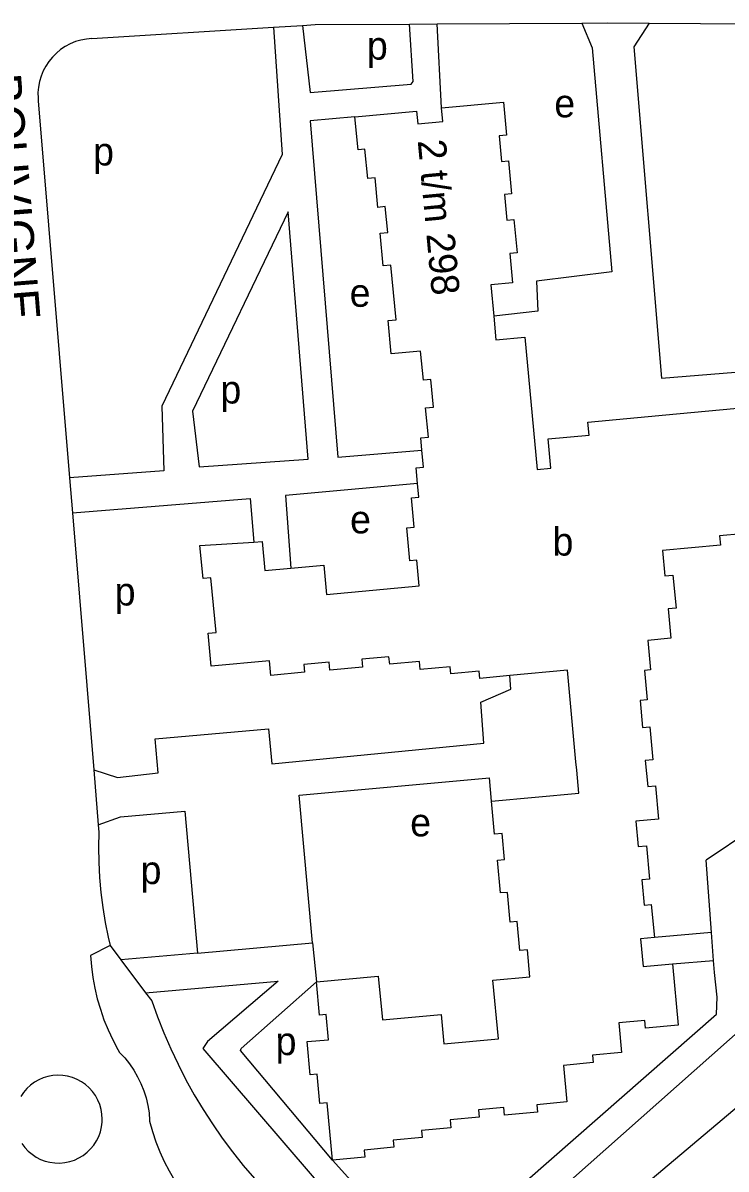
# Model space of a CAD drawing. Extents: x 157794 to 159375, y 380877 to 382306.
# Drawn here: x 158233.2 to 158333.5, y 381095.2 to 381258.6 of the extents above; entities that cross this region are included whole.
import ezdxf

# ---------------------------------------------------------------- set-up
doc = ezdxf.new("R2010")
doc.units = 0
for name, color, linetype in [('BLT_Basislijn', 7, 'Continuous'), ('BLT_Bebouwing', 7, 'Continuous'), ('BLT_Centroide', 7, 'Continuous'), ('BLT_Huisnummer_reeks', 7, 'Continuous'), ('BLT_Straatnaam', 7, 'Continuous')]:
    doc.layers.add(name, color=color, linetype=linetype)

msp = doc.modelspace()

# ---------------------------------------------------------------- linework, layer by layer
at = {"layer": 'BLT_Basislijn'}
for p, q in [((158243.03, 381256.36), (158268.94, 381257.97)), ((158268.94, 381257.97), (158273.07, 381258.22)), ((158288.34, 381258.42), (158292.29, 381258.44)), ((158292.29, 381258.44), (158312.89, 381258.56)), ((158292.9, 381246.48), (158292.29, 381258.44)), ((158322.49, 381258.55), (158363.87, 381258.34)), ((158235.37, 381247.47), (158239.83, 381193.72)), ((158239.83, 381193.72), (158240.24, 381188.74)), ((158240.24, 381188.74), (158243.28, 381152.07)), ((158243.28, 381152.07), (158243.93, 381144.25)), ((158300.04, 381147.61), (158299.74, 381150.93)), ((158343.5, 381147.91), (158330.66, 381139.21)), ((158243.93, 381144.25), (158244.01, 381143.21)), ((158331.42, 381128.87), (158330.66, 381139.21)), ((158331.42, 381128.87), (158323.26, 381128.16)), ((158245.62, 381127.05), (158242.83, 381125.61)), ((158245.62, 381127.05), (158247.15, 381125.01)), ((158274.48, 381127.4), (158275.06, 381121.86)), ((158258.07, 381125.96), (158247.15, 381125.01)), ((158247.15, 381125.01), (158250.69, 381120.3)), ((158325.83, 381124.43), (158331.71, 381124.89)), ((158250.69, 381120.3), (158269.57, 381121.95)), ((158250.69, 381120.3), (158251.55, 381119.17))]:
    msp.add_line(p, q, dxfattribs=at)
for points in [[(158268.94, 381257.97), (158270.17, 381239.84), (158252.98, 381203.96), (158253.3, 381194.7), (158239.83, 381193.72)], [(158273.07, 381258.22), (158274.16, 381248.67), (158288.55, 381249.83), (158288.86, 381250.21), (158288.34, 381258.42)], [(158273.07, 381258.22), (158274.88, 381258.34), (158288.34, 381258.42)], [(158312.89, 381258.56), (158314.38, 381255.03), (158317.19, 381223.11), (158306.42, 381221.76), (158306.64, 381217.47), (158300.35, 381216.76)], [(158312.89, 381258.56), (158316.61, 381258.58), (158322.49, 381258.55)], [(158322.49, 381258.55), (158320.33, 381255.19), (158324.26, 381207.94), (158344.81, 381209.61)], [(158243.03, 381256.36), (158242.23, 381256.29), (158241.44, 381256.14), (158240.68, 381255.92), (158239.94, 381255.61), (158239.23, 381255.24), (158238.56, 381254.8), (158237.95, 381254.29), (158237.38, 381253.72), (158236.88, 381253.1), (158236.43, 381252.44), (158236.06, 381251.73), (158235.76, 381250.99), (158235.54, 381250.22), (158235.39, 381249.43), (158235.33, 381248.64), (158235.34, 381247.84), (158235.37, 381247.47)], [(158280.55, 381245.2), (158274.15, 381244.64), (158278.12, 381196.66), (158290.1, 381197.66)], [(158271.04, 381231.66), (158257.39, 381203.25), (158258.32, 381195.29), (158273.89, 381196.36), (158271.04, 381231.66)], [(158289.48, 381192.92), (158270.64, 381191.19), (158271.41, 381180.84)], [(158240.24, 381188.74), (158265.6, 381190.76), (158266.13, 381184.57)], [(158243.28, 381152.07), (158246.66, 381151.01), (158252.46, 381151.67), (158252.03, 381156.53), (158268.23, 381157.94), (158268.7, 381152.93), (158298.93, 381155.88), (158298.48, 381161.72), (158302.78, 381163.59), (158302.66, 381165.52)], [(158274.48, 381127.4), (158272.6, 381148.49), (158299.74, 381150.93)], [(158243.93, 381144.25), (158247.09, 381145.38), (158256.28, 381146.19), (158258.07, 381125.96)], [(158244.01, 381143.21), (158243.96, 381141.06), (158243.99, 381138.91), (158244.11, 381136.75), (158244.3, 381134.61), (158244.57, 381132.47), (158244.91, 381130.34), (158245.34, 381128.23), (158245.62, 381127.05)], [(158331.71, 381124.89), (158331.46, 381128.24), (158331.42, 381128.87)], [(158258.07, 381125.96), (158274.48, 381127.4)], [(158242.83, 381125.61), (158242.95, 381124.05), (158243.15, 381122.5), (158243.43, 381120.96), (158243.79, 381119.44), (158244.23, 381117.94), (158244.74, 381116.46), (158245.33, 381115.02), (158245.99, 381113.6), (158246.73, 381112.22), (158246.97, 381111.79)], [(158277.33, 381096.43), (158290.9, 381081.39), (158291.62, 381081.75), (158332.11, 381117.25), (158332.2, 381119.68), (158331.84, 381123.19), (158331.71, 381124.89)], [(158269.57, 381121.95), (158259.53, 381113.33), (158258.83, 381112.37), (158289.77, 381076.36), (158291.12, 381075.66), (158336.49, 381115.85)], [(158277.33, 381096.43), (158264.24, 381112.05), (158264.3, 381112.37), (158275.06, 381121.86)], [(158251.55, 381119.17), (158252.38, 381116.86), (158253.28, 381114.57), (158254.26, 381112.32), (158255.31, 381110.1), (158256.43, 381107.91), (158257.63, 381105.76), (158258.89, 381103.66), (158260.22, 381101.59), (158261.62, 381099.57), (158263.08, 381097.6), (158264.61, 381095.67), (158266.2, 381093.8), (158267.84, 381091.98), (158267.98, 381091.83)], [(158246.97, 381111.79), (158247.71, 381111), (158248.39, 381110.15), (158249, 381109.26), (158249.54, 381108.32), (158250.02, 381107.34), (158250.42, 381106.34), (158250.75, 381105.3), (158251, 381104.25), (158251.17, 381103.18), (158251.26, 381102.1), (158251.26, 381101.97)], [(158244.49, 381102.28), (158244.45, 381102.98), (158244.33, 381103.68), (158244.13, 381104.36), (158243.86, 381105.01), (158243.52, 381105.63), (158243.1, 381106.21), (158242.63, 381106.73), (158242.1, 381107.2), (158241.52, 381107.61), (158240.9, 381107.94), (158240.24, 381108.21), (158239.56, 381108.4), (158238.86, 381108.51), (158238.15, 381108.54), (158237.45, 381108.49), (158236.75, 381108.36), (158236.08, 381108.16), (158235.43, 381107.88), (158234.81, 381107.53), (158234.24, 381107.11), (158233.72, 381106.63), (158233.26, 381106.09), (158232.86, 381105.51)], [(158289.99, 381065.95), (158304.19, 381078.05), (158337.15, 381105.79)], [(158233.02, 381098.8), (158233.45, 381098.23), (158233.93, 381097.72), (158234.48, 381097.27), (158235.07, 381096.87), (158235.7, 381096.55), (158236.36, 381096.3), (158237.04, 381096.13), (158237.74, 381096.04), (158238.45, 381096.02), (158239.16, 381096.09), (158239.85, 381096.23), (158240.52, 381096.45), (158241.16, 381096.75), (158241.77, 381097.11), (158242.33, 381097.55), (158242.84, 381098.04), (158243.29, 381098.59), (158243.67, 381099.18), (158243.99, 381099.81), (158244.23, 381100.48), (158244.39, 381101.17), (158244.48, 381101.87), (158244.49, 381102.28)], [(158251.26, 381101.97), (158251.67, 381100.5), (158252.15, 381099.05), (158252.71, 381097.64), (158253.35, 381096.25), (158254.05, 381094.9), (158254.82, 381093.58), (158255.25, 381092.92)]]:
    msp.add_lwpolyline(points, dxfattribs=at)
at = {"layer": 'BLT_Bebouwing'}
for p, q in [((158313.78, 381201.67), (158326.39, 381202.85)), ((158312.18, 381152.05), (158312.07, 381153.22))]:
    msp.add_line(p, q, dxfattribs=at)
for points in [[(158280.55, 381245.2), (158289.32, 381246.01), (158289.49, 381244.19), (158293.08, 381244.52), (158292.9, 381246.48)], [(158292.9, 381246.48), (158301.71, 381247.29), (158302.15, 381242.56), (158301.12, 381242.47), (158301.46, 381238.82), (158302.43, 381238.91), (158302.87, 381234.2), (158301.86, 381234.11), (158302.19, 381230.47), (158303.23, 381230.57), (158303.68, 381225.8), (158302.63, 381225.7), (158303.02, 381221.51), (158299.93, 381221.22), (158300.35, 381216.76)], [(158290.1, 381197.66), (158289.94, 381199.43), (158291.02, 381199.53), (158290.63, 381203.68), (158291.74, 381203.78), (158291.37, 381207.73), (158290.3, 381207.63), (158289.91, 381211.79), (158285.72, 381211.4), (158285.28, 381216.14), (158286.4, 381216.25), (158285.68, 381224.04), (158284.55, 381223.94), (158284.12, 381228.59), (158285.21, 381228.69), (158284.87, 381232.39), (158283.83, 381232.29), (158283.44, 381236.49), (158282.36, 381236.39), (158281.97, 381240.57), (158280.98, 381240.48), (158280.55, 381245.2)], [(158300.35, 381216.76), (158300.66, 381213.39), (158304.77, 381213.77), (158306.52, 381194.9), (158308.5, 381195.08), (158308.11, 381199.27), (158313.95, 381199.82), (158313.78, 381201.67)], [(158326.39, 381202.85), (158337.15, 381203.85), (158337.34, 381201.88), (158345.45, 381202.63), (158344.81, 381209.61)], [(158289.48, 381192.92), (158289.27, 381195.15), (158290.33, 381195.25), (158290.1, 381197.66)], [(158271.41, 381180.84), (158276.1, 381181.27), (158276.49, 381177.07), (158289.69, 381178.3), (158289.35, 381181.97), (158288.38, 381181.88), (158287.94, 381186.57), (158289.01, 381186.67), (158288.62, 381190.88), (158289.66, 381190.97), (158289.48, 381192.92)], [(158335.72, 381185.74), (158332.56, 381185.44), (158332.68, 381184.1), (158324.4, 381183.34), (158324.73, 381179.74), (158325.9, 381179.85), (158326.34, 381175.12), (158325.23, 381175.02), (158325.62, 381170.85), (158322.32, 381170.54), (158322.71, 381166.34), (158321.85, 381166.26), (158322.24, 381162.05), (158321.21, 381161.95), (158321.57, 381158.12), (158322.59, 381158.22), (158323.02, 381153.53), (158321.96, 381153.43), (158322.3, 381149.72), (158323.41, 381149.82), (158323.85, 381145.07), (158320.59, 381144.77), (158320.93, 381141.16), (158322.11, 381141.27), (158322.55, 381136.51), (158321.46, 381136.41), (158321.8, 381132.77), (158322.82, 381132.87), (158323.26, 381128.16)], [(158302.66, 381165.52), (158298.37, 381165.12), (158298.27, 381166.16), (158294.2, 381165.78), (158294.11, 381166.79), (158289.86, 381166.4), (158289.76, 381167.52), (158285.5, 381167.13), (158285.4, 381168.21), (158281.52, 381167.85), (158281.62, 381166.74), (158276.97, 381166.3), (158276.87, 381167.45), (158273.23, 381167.11), (158273.33, 381165.99), (158268.53, 381165.55), (158268.34, 381167.62), (158260.02, 381166.85), (158259.59, 381171.56), (158260.73, 381171.66), (158260, 381179.48), (158258.87, 381179.37), (158258.43, 381184.07), (158266.13, 381184.57)], [(158266.13, 381184.57), (158267.32, 381184.65), (158267.7, 381180.49), (158271.41, 381180.84)], [(158312.07, 381153.22), (158310.86, 381166.28), (158302.66, 381165.52)], [(158300.04, 381147.61), (158312.48, 381148.76), (158312.18, 381152.05)], [(158300.23, 381122.08), (158305.5, 381122.57), (158305.14, 381126.41), (158304.07, 381126.31), (158303.69, 381130.45), (158302.7, 381130.36), (158302.3, 381134.62), (158301.29, 381134.53), (158300.86, 381139.21), (158301.89, 381139.3), (158301.54, 381143), (158300.47, 381142.9), (158300.04, 381147.61)], [(158323.26, 381128.16), (158321.28, 381127.98), (158321.65, 381124.04), (158325.83, 381124.43)], [(158325.83, 381124.43), (158326.65, 381115.67), (158321.97, 381115.24), (158321.87, 381116.35), (158318.18, 381116.01), (158318.57, 381111.78), (158314.41, 381111.4), (158314.51, 381110.34), (158310.3, 381109.95), (158310.79, 381104.73), (158306.49, 381104.33), (158306.58, 381103.29), (158301.89, 381102.85), (158301.79, 381103.96), (158298.18, 381103.62), (158298.27, 381102.58), (158294.13, 381102.19), (158294.24, 381101.03), (158290.04, 381100.64), (158290.13, 381099.68), (158285.98, 381099.29), (158286.07, 381098.27), (158281.84, 381097.87), (158281.93, 381096.86), (158277.33, 381096.43)], [(158277.33, 381096.43), (158276.57, 381104.62), (158275.54, 381104.52), (158275.15, 381108.68), (158274.16, 381108.59), (158273.72, 381113.33), (158276.75, 381113.61), (158276.42, 381117.18), (158275.5, 381117.1), (158275.06, 381121.86)], [(158275.06, 381121.86), (158283.86, 381122.68), (158284.45, 381116.42), (158292.83, 381117.2), (158293.22, 381113.01), (158301.01, 381113.73), (158300.23, 381122.08)]]:
    msp.add_lwpolyline(points, dxfattribs=at)

# ---------------------------------------------------------------- texts
at = {"layer": 'BLT_Centroide'}
for s, p in [('p', (158282.25, 381253.35)), ('e', (158308.98, 381245.12)), ('p', (158243.19, 381238.26)), ('e', (158279.79, 381218.11)), ('p', (158261.35, 381204.32)), ('e', (158279.85, 381185.8)), ('b', (158308.73, 381182.64)), ('p', (158246.27, 381175.52)), ('e', (158288.42, 381142.6)), ('p', (158249.97, 381135.8)), ('p', (158269.23, 381111.41))]:
    msp.add_text(s, height=4, dxfattribs=at).set_placement(p)
at = {"layer": 'BLT_Huisnummer_reeks'}
msp.add_text('2 t/m 298', height=4, rotation=275.2895, dxfattribs=at).set_placement((158289.49, 381241.81))
at = {"layer": 'BLT_Straatnaam'}
msp.add_text('BOUVIGNE', height=5, rotation=274.5867, dxfattribs=at).set_placement((158227.89, 381251.18))

doc.saveas('drawing.dxf')
